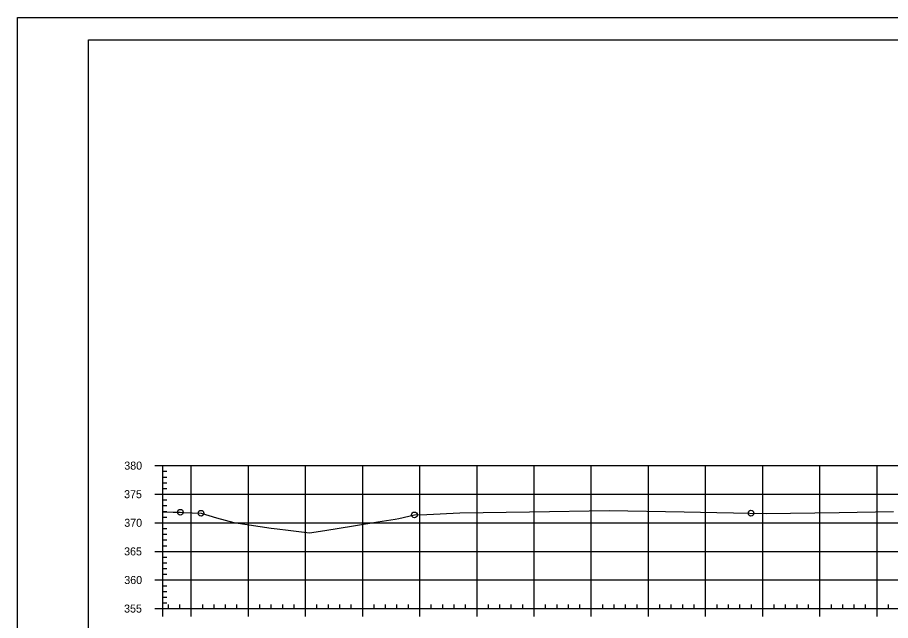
# Model space of a CAD drawing. Extents: x 1359801 to 1362404, y 372415 to 374228.
# Drawn here: x 1360417.1 to 1360569.9, y 374122.5 to 374228 of the extents above; entities that cross this region are included whole.
import ezdxf

# ---------------------------------------------------------------- set-up
doc = ezdxf.new("R2010")
doc.units = 0
for name, color, linetype in [('S_DRG_PT_SYM', 7, 'Continuous'), ('S_MAILBOX', 7, 'Continuous'), ('S_PRIMARY_CTL', 7, 'Continuous'), ('S_SHOULDER', 7, 'Continuous'), ('S_UTL_PT_SYM', 7, 'Continuous'), ('S_WATER_UTILITIES', 7, 'Continuous')]:
    doc.layers.add(name, color=color, linetype=linetype)

msp = doc.modelspace()

# ---------------------------------------------------------------- linework, layer by layer
at = {"layer": 'S_DRG_PT_SYM'}
msp.add_lwpolyline([(1360442.53, 374141.51), (1360444.35, 374141.48), (1360445.62, 374141.45), (1360446.1, 374141.42), (1360449.24, 374141.28), (1360451.97, 374140.49), (1360454.99, 374139.65), (1360461.5, 374138.68), (1360462.57, 374138.53), (1360464.46, 374138.31), (1360468.2, 374137.88), (1360470.93, 374138.29), (1360475.91, 374139.06), (1360480.15, 374139.75), (1360483.2, 374140.24), (1360483.86, 374140.39), (1360486.58, 374140.99), (1360488.74, 374141.08), (1360494.5, 374141.34), (1360506.72, 374141.53), (1360520.64, 374141.77), (1360533.76, 374141.51), (1360548.15, 374141.24), (1360560.9, 374141.43), (1360570.4, 374141.56)], dxfattribs=at)
at = {"layer": 'S_MAILBOX'}
for p, q in [((1360442.53, 374149.61), (1360732.53, 374149.61)), ((1360442.53, 374124.61), (1360442.53, 374149.61)), ((1360447.53, 374124.61), (1360447.53, 374149.61)), ((1360457.53, 374124.61), (1360457.53, 374149.61)), ((1360467.53, 374124.61), (1360467.53, 374149.61)), ((1360477.53, 374124.61), (1360477.53, 374149.61)), ((1360487.53, 374124.61), (1360487.53, 374149.61)), ((1360497.53, 374124.61), (1360497.53, 374149.61)), ((1360507.53, 374124.61), (1360507.53, 374149.61)), ((1360517.53, 374124.61), (1360517.53, 374149.61)), ((1360527.53, 374124.61), (1360527.53, 374149.61)), ((1360537.53, 374124.61), (1360537.53, 374149.61)), ((1360547.53, 374124.61), (1360547.53, 374149.61)), ((1360557.53, 374124.61), (1360557.53, 374149.61)), ((1360567.53, 374124.61), (1360567.53, 374149.61)), ((1360442.53, 374144.61), (1360732.53, 374144.61)), ((1360442.53, 374139.61), (1360732.53, 374139.61)), ((1360442.53, 374134.61), (1360732.53, 374134.61)), ((1360442.53, 374129.61), (1360732.53, 374129.61)), ((1360442.53, 374124.61), (1360732.53, 374124.61))]:
    msp.add_line(p, q, dxfattribs=at)
at = {"layer": 'S_SHOULDER'}
msp.add_line((1360417.13, 374227.97), (1360750.46, 374227.97), dxfattribs=at)
for points in [[(1360417.12, 374227.97), (1360750.46, 374227.97), (1360750.46, 374014.63), (1360417.12, 374014.63)], [(1360663.45, 374224.07), (1360663.45, 374214.19), (1360699.18, 374214.19), (1360699.18, 374211.27), (1360722.38, 374211.27), (1360722.38, 374186.94), (1360745.71, 374186.94), (1360745.71, 374018.61), (1360429.53, 374018.61), (1360429.53, 374224.07)]]:
    msp.add_lwpolyline(points, close=True, dxfattribs=at)
for centre in [(1360445.62, 374141.45), (1360449.24, 374141.28), (1360486.58, 374140.99), (1360545.47, 374141.29)]:
    msp.add_circle(centre, 0.5, dxfattribs=at)
at = {"layer": 'S_UTL_PT_SYM'}
for p, q in [((1360429.53, 374224.07), (1360745.71, 374224.07)), ((1360429.53, 374018.61), (1360429.53, 374224.07))]:
    msp.add_line(p, q, dxfattribs=at)
at = {"layer": 'S_WATER_UTILITIES'}
for p, q in [((1360441.13, 374149.61), (1360442.53, 374149.61)), ((1360442.53, 374124.61), (1360442.53, 374149.61)), ((1360442.53, 374148.61), (1360443.23, 374148.61)), ((1360442.53, 374147.61), (1360443.23, 374147.61)), ((1360442.53, 374146.61), (1360443.23, 374146.61)), ((1360442.53, 374145.61), (1360443.23, 374145.61)), ((1360441.13, 374144.61), (1360442.53, 374144.61)), ((1360442.53, 374143.61), (1360443.23, 374143.61)), ((1360442.53, 374142.61), (1360443.23, 374142.61)), ((1360442.53, 374141.61), (1360443.23, 374141.61)), ((1360441.13, 374139.61), (1360442.53, 374139.61)), ((1360442.53, 374140.61), (1360443.23, 374140.61)), ((1360442.53, 374138.61), (1360443.23, 374138.61)), ((1360442.53, 374137.61), (1360443.23, 374137.61)), ((1360442.53, 374136.61), (1360443.23, 374136.61)), ((1360442.53, 374135.61), (1360443.23, 374135.61)), ((1360441.13, 374134.61), (1360442.53, 374134.61)), ((1360442.53, 374133.61), (1360443.23, 374133.61)), ((1360442.53, 374132.61), (1360443.23, 374132.61)), ((1360442.53, 374131.61), (1360443.23, 374131.61)), ((1360442.53, 374130.61), (1360443.23, 374130.61)), ((1360441.13, 374129.61), (1360442.53, 374129.61)), ((1360442.53, 374128.61), (1360443.23, 374128.61)), ((1360442.53, 374127.61), (1360443.23, 374127.61)), ((1360442.53, 374126.61), (1360443.23, 374126.61)), ((1360441.13, 374124.61), (1360442.53, 374124.61)), ((1360442.53, 374125.61), (1360443.23, 374125.61)), ((1360442.53, 374124.61), (1360442.53, 374125.31)), ((1360442.53, 374124.61), (1360732.53, 374124.61)), ((1360442.53, 374123.21), (1360442.53, 374124.61)), ((1360443.53, 374124.61), (1360443.53, 374125.31)), ((1360445.53, 374124.61), (1360445.53, 374125.31)), ((1360447.53, 374123.21), (1360447.53, 374124.61)), ((1360449.53, 374124.61), (1360449.53, 374125.31)), ((1360451.53, 374124.61), (1360451.53, 374125.31)), ((1360453.53, 374124.61), (1360453.53, 374125.31)), ((1360455.53, 374124.61), (1360455.53, 374125.31)), ((1360457.53, 374123.21), (1360457.53, 374124.61)), ((1360459.53, 374124.61), (1360459.53, 374125.31)), ((1360461.53, 374124.61), (1360461.53, 374125.31)), ((1360463.53, 374124.61), (1360463.53, 374125.31)), ((1360465.53, 374124.61), (1360465.53, 374125.31)), ((1360467.53, 374123.21), (1360467.53, 374124.61)), ((1360469.53, 374124.61), (1360469.53, 374125.31)), ((1360471.53, 374124.61), (1360471.53, 374125.31)), ((1360473.53, 374124.61), (1360473.53, 374125.31)), ((1360475.53, 374124.61), (1360475.53, 374125.31)), ((1360477.53, 374123.21), (1360477.53, 374124.61)), ((1360479.53, 374124.61), (1360479.53, 374125.31)), ((1360481.53, 374124.61), (1360481.53, 374125.31)), ((1360483.53, 374124.61), (1360483.53, 374125.31)), ((1360485.53, 374124.61), (1360485.53, 374125.31)), ((1360487.53, 374123.21), (1360487.53, 374124.61)), ((1360489.53, 374124.61), (1360489.53, 374125.31)), ((1360491.53, 374124.61), (1360491.53, 374125.31)), ((1360493.53, 374124.61), (1360493.53, 374125.31)), ((1360495.53, 374124.61), (1360495.53, 374125.31)), ((1360497.53, 374123.21), (1360497.53, 374124.61)), ((1360499.53, 374124.61), (1360499.53, 374125.31)), ((1360501.53, 374124.61), (1360501.53, 374125.31)), ((1360503.53, 374124.61), (1360503.53, 374125.31)), ((1360505.53, 374124.61), (1360505.53, 374125.31)), ((1360507.53, 374123.21), (1360507.53, 374124.61)), ((1360509.53, 374124.61), (1360509.53, 374125.31)), ((1360511.53, 374124.61), (1360511.53, 374125.31)), ((1360513.53, 374124.61), (1360513.53, 374125.31)), ((1360515.53, 374124.61), (1360515.53, 374125.31)), ((1360517.53, 374123.21), (1360517.53, 374124.61)), ((1360519.53, 374124.61), (1360519.53, 374125.31)), ((1360521.53, 374124.61), (1360521.53, 374125.31)), ((1360523.53, 374124.61), (1360523.53, 374125.31)), ((1360525.53, 374124.61), (1360525.53, 374125.31)), ((1360527.53, 374123.21), (1360527.53, 374124.61)), ((1360529.53, 374124.61), (1360529.53, 374125.31)), ((1360531.53, 374124.61), (1360531.53, 374125.31)), ((1360533.53, 374124.61), (1360533.53, 374125.31)), ((1360535.53, 374124.61), (1360535.53, 374125.31)), ((1360537.53, 374123.21), (1360537.53, 374124.61)), ((1360539.53, 374124.61), (1360539.53, 374125.31)), ((1360541.53, 374124.61), (1360541.53, 374125.31)), ((1360543.53, 374124.61), (1360543.53, 374125.31)), ((1360545.53, 374124.61), (1360545.53, 374125.31)), ((1360547.53, 374123.21), (1360547.53, 374124.61)), ((1360549.53, 374124.61), (1360549.53, 374125.31)), ((1360551.53, 374124.61), (1360551.53, 374125.31)), ((1360553.53, 374124.61), (1360553.53, 374125.31)), ((1360555.53, 374124.61), (1360555.53, 374125.31)), ((1360557.53, 374123.21), (1360557.53, 374124.61)), ((1360559.53, 374124.61), (1360559.53, 374125.31)), ((1360561.53, 374124.61), (1360561.53, 374125.31)), ((1360563.53, 374124.61), (1360563.53, 374125.31)), ((1360565.53, 374124.61), (1360565.53, 374125.31)), ((1360567.53, 374123.21), (1360567.53, 374124.61)), ((1360569.53, 374124.61), (1360569.53, 374125.31))]:
    msp.add_line(p, q, dxfattribs=at)

# ---------------------------------------------------------------- texts
at = {"layer": 'S_PRIMARY_CTL'}
for s, p in [('380', (1360435.81, 374148.91)), ('375', (1360435.78, 374143.91)), ('370', (1360435.81, 374138.91)), ('365', (1360435.78, 374133.91)), ('360', (1360435.81, 374128.91)), ('355', (1360435.78, 374123.91))]:
    msp.add_text(s, height=1.4, dxfattribs=at).set_placement(p)
at = {"layer": 'S_SHOULDER'}
msp.add_text('+', height=0.1, dxfattribs=at).set_placement((1360494.46, 374141.29))

doc.saveas('drawing.dxf')
